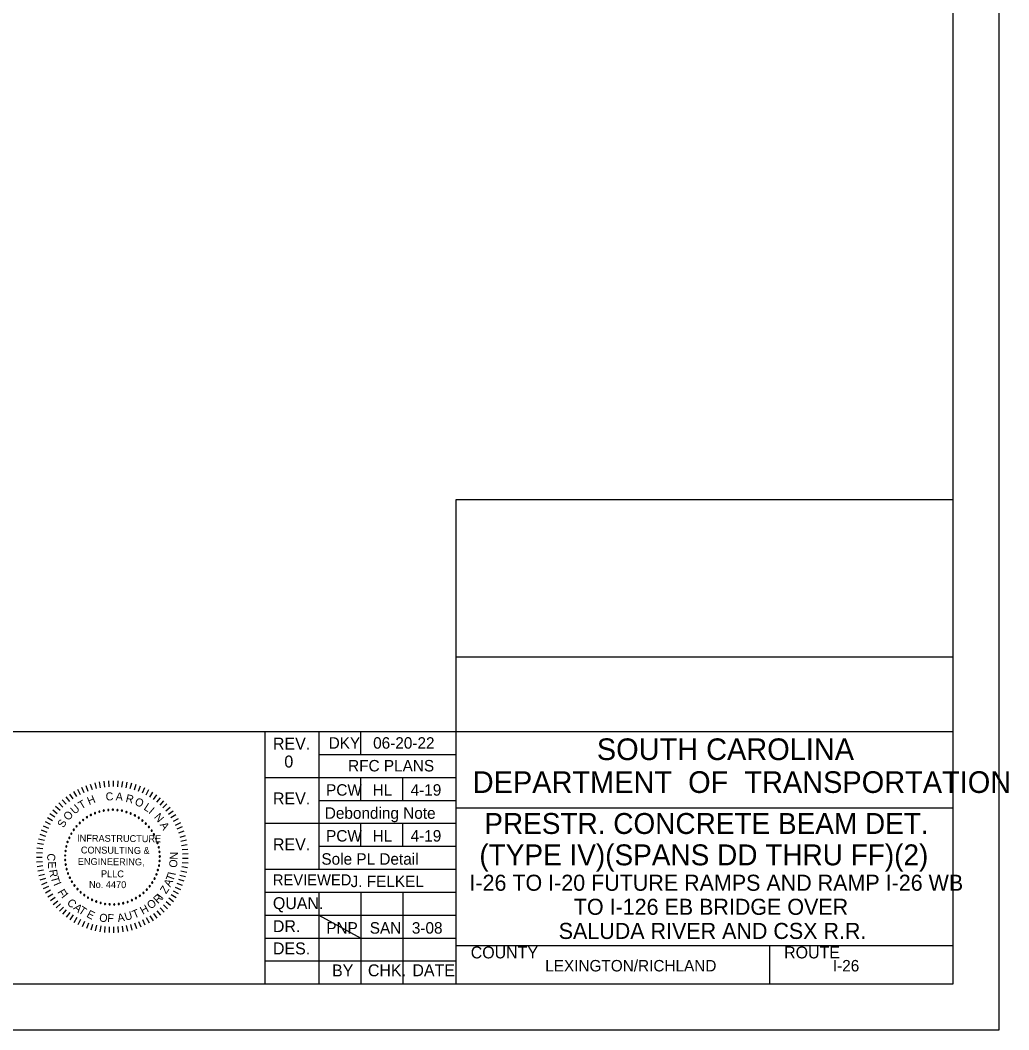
# Model space of a CAD drawing. Extents: x -50.5 to -14.4, y -52.6 to -30.6.
# Drawn here: x -25.19 to -14.41, y -52.58 to -41.58 of the extents above; entities that cross this region are included whole.
import ezdxf

# ---------------------------------------------------------------- set-up
doc = ezdxf.new("R2010")
doc.units = 0
for name, color, linetype in [('BR_BORDER LINES', 7, 'Continuous'), ('BR_TEXT', 7, 'Continuous'), ('Level 31', 7, 'Continuous')]:
    doc.layers.add(name, color=color, linetype=linetype)

msp = doc.modelspace()

# ---------------------------------------------------------------- linework, layer by layer
at = {"layer": 'BR_BORDER LINES'}
for p, q in [((-15.019, -52.081), (-15.019, -31.081)), ((-20.436, -52.081), (-20.436, -46.804)), ((-20.436, -46.804), (-15.019, -46.804)), ((-20.436, -48.519), (-15.019, -48.519)), ((-27.885, -49.331), (-22.52, -49.331)), ((-22.52, -52.081), (-22.52, -49.331)), ((-22.52, -49.331), (-15.019, -49.331)), ((-21.936, -49.331), (-21.936, -50.831)), ((-21.478, -49.581), (-21.478, -49.331)), ((-21.936, -49.581), (-20.436, -49.581)), ((-22.52, -49.831), (-20.436, -49.831)), ((-21.478, -50.081), (-21.478, -49.831)), ((-21.019, -50.081), (-21.019, -49.831)), ((-21.936, -50.081), (-20.436, -50.081)), ((-20.436, -50.164), (-20.436, -50.164)), ((-20.436, -50.164), (-15.019, -50.164)), ((-22.52, -50.331), (-20.436, -50.331)), ((-21.478, -50.581), (-21.478, -50.331)), ((-21.019, -50.581), (-21.019, -50.331)), ((-21.936, -50.581), (-20.436, -50.581)), ((-22.52, -50.831), (-20.436, -50.831)), ((-22.52, -51.081), (-20.436, -51.081)), ((-21.936, -51.081), (-21.936, -52.081)), ((-21.478, -51.081), (-21.478, -52.081)), ((-21.019, -51.081), (-21.019, -52.081)), ((-22.52, -51.331), (-20.436, -51.331)), ((-22.52, -51.581), (-20.436, -51.581)), ((-20.436, -51.664), (-15.019, -51.664)), ((-20.339, -51.664), (-15.019, -51.664)), ((-17.019, -52.081), (-17.019, -51.664)), ((-22.52, -51.831), (-20.436, -51.831)), ((-48.685, -52.081), (-15.019, -52.081))]:
    msp.add_line(p, q, dxfattribs=at)
at = {"layer": 'BR_TEXT'}
for p, q in [((-24.522, -49.939), (-24.496, -49.997)), ((-24.475, -49.92), (-24.453, -49.979)), ((-24.427, -49.903), (-24.408, -49.964)), ((-24.378, -49.89), (-24.363, -49.952)), ((-24.329, -49.88), (-24.318, -49.943)), ((-24.279, -49.873), (-24.272, -49.936)), ((-24.229, -49.869), (-24.225, -49.932)), ((-24.178, -49.867), (-24.179, -49.931)), ((-24.128, -49.87), (-24.132, -49.933)), ((-24.077, -49.875), (-24.086, -49.938)), ((-24.028, -49.883), (-24.04, -49.945)), ((-23.978, -49.894), (-23.994, -49.956)), ((-23.93, -49.908), (-23.95, -49.969)), ((-23.882, -49.925), (-23.906, -49.984)), ((-24.694, -50.042), (-24.655, -50.092)), ((-24.654, -50.012), (-24.618, -50.065)), ((-24.611, -49.985), (-24.578, -50.04)), ((-24.567, -49.96), (-24.538, -50.017)), ((-23.836, -49.945), (-23.863, -50.003)), ((-23.791, -49.968), (-23.821, -50.024)), ((-23.747, -49.993), (-23.781, -50.047)), ((-23.705, -50.021), (-23.742, -50.073)), ((-24.805, -50.146), (-24.757, -50.188)), ((-24.77, -50.109), (-24.725, -50.154)), ((-24.733, -50.074), (-24.691, -50.122)), ((-23.665, -50.052), (-23.705, -50.101)), ((-23.627, -50.085), (-23.67, -50.132)), ((-23.591, -50.12), (-23.636, -50.164)), ((-23.557, -50.157), (-23.605, -50.199)), ((-24.894, -50.267), (-24.84, -50.3)), ((-24.867, -50.225), (-24.815, -50.261)), ((-24.837, -50.184), (-24.787, -50.223)), ((-23.525, -50.197), (-23.576, -50.235)), ((-23.496, -50.238), (-23.549, -50.273)), ((-24.941, -50.357), (-24.883, -50.383)), ((-24.919, -50.311), (-24.863, -50.341)), ((-23.469, -50.281), (-23.524, -50.313)), ((-23.445, -50.325), (-23.502, -50.354)), ((-23.424, -50.371), (-23.483, -50.396)), ((-24.977, -50.451), (-24.916, -50.47)), ((-24.961, -50.403), (-24.901, -50.426)), ((-23.406, -50.418), (-23.466, -50.44)), ((-23.391, -50.466), (-23.452, -50.484)), ((-25.008, -50.599), (-24.945, -50.606)), ((-25.001, -50.549), (-24.938, -50.56)), ((-24.99, -50.5), (-24.928, -50.515)), ((-23.378, -50.515), (-23.44, -50.529)), ((-23.369, -50.565), (-23.431, -50.575)), ((-25.014, -50.7), (-24.95, -50.699)), ((-25.012, -50.649), (-24.949, -50.653)), ((-23.362, -50.615), (-23.426, -50.621)), ((-23.359, -50.665), (-23.422, -50.668)), ((-25.012, -50.75), (-24.948, -50.746)), ((-25.007, -50.801), (-24.944, -50.792)), ((-23.367, -50.816), (-23.43, -50.807)), ((-23.361, -50.766), (-23.425, -50.761)), ((-23.358, -50.716), (-23.422, -50.714)), ((-24.999, -50.85), (-24.936, -50.838)), ((-24.988, -50.9), (-24.926, -50.884)), ((-24.974, -50.948), (-24.913, -50.929)), ((-23.388, -50.915), (-23.449, -50.898)), ((-23.376, -50.866), (-23.438, -50.853)), ((-24.957, -50.996), (-24.898, -50.973)), ((-24.937, -51.042), (-24.88, -51.016)), ((-23.441, -51.056), (-23.499, -51.029)), ((-23.421, -51.01), (-23.48, -50.986)), ((-23.403, -50.963), (-23.463, -50.943)), ((-24.915, -51.087), (-24.859, -51.057)), ((-24.89, -51.131), (-24.835, -51.098)), ((-24.862, -51.173), (-24.81, -51.136)), ((-23.519, -51.186), (-23.571, -51.148)), ((-23.491, -51.144), (-23.544, -51.11)), ((-23.465, -51.101), (-23.52, -51.07)), ((-24.831, -51.214), (-24.782, -51.174)), ((-24.798, -51.252), (-24.751, -51.209)), ((-24.763, -51.288), (-24.719, -51.243)), ((-23.62, -51.299), (-23.664, -51.253)), ((-23.584, -51.263), (-23.63, -51.22)), ((-23.551, -51.226), (-23.6, -51.185)), ((-24.726, -51.322), (-24.685, -51.274)), ((-24.687, -51.354), (-24.648, -51.303)), ((-24.646, -51.383), (-24.61, -51.33)), ((-24.603, -51.41), (-24.571, -51.355)), ((-23.783, -51.418), (-23.814, -51.362)), ((-23.739, -51.392), (-23.774, -51.338)), ((-23.698, -51.363), (-23.735, -51.312)), ((-23.658, -51.332), (-23.698, -51.283)), ((-24.559, -51.434), (-24.53, -51.377)), ((-24.513, -51.456), (-24.488, -51.397)), ((-24.466, -51.474), (-24.444, -51.414)), ((-24.418, -51.49), (-24.4, -51.429)), ((-24.369, -51.502), (-24.355, -51.44)), ((-24.319, -51.512), (-24.309, -51.449)), ((-24.269, -51.519), (-24.263, -51.455)), ((-24.219, -51.522), (-24.217, -51.459)), ((-24.169, -51.523), (-24.17, -51.459)), ((-24.118, -51.52), (-24.123, -51.457)), ((-24.068, -51.514), (-24.077, -51.451)), ((-24.018, -51.506), (-24.031, -51.443)), ((-23.969, -51.494), (-23.986, -51.433)), ((-23.921, -51.479), (-23.941, -51.419)), ((-23.874, -51.462), (-23.898, -51.403)), ((-23.827, -51.441), (-23.855, -51.384))]:
    msp.add_line(p, q, dxfattribs=at)
for centre, start, end in [((-24.464, -50.265), 32.7576, 212.7576), ((-24.464, -50.265), 212.7576, 32.7576), ((-24.421, -50.24), 27.2191, 207.2191), ((-24.421, -50.24), 207.2191, 27.2191), ((-24.375, -50.22), 21.6807, 201.6807), ((-24.375, -50.22), 201.6807, 21.6807), ((-24.328, -50.204), 16.1422, 196.1422), ((-24.328, -50.204), 196.1422, 16.1422), ((-24.28, -50.192), 10.6038, 190.6038), ((-24.28, -50.192), 190.6038, 10.6038), ((-24.23, -50.186), 5.0653, 185.0653), ((-24.23, -50.186), 185.0653, 5.0653), ((-24.181, -50.184), 359.5268, 179.5268), ((-24.181, -50.184), 179.5268, 359.5268), ((-24.131, -50.187), 353.9884, 173.9884), ((-24.131, -50.187), 173.9884, 353.9884), ((-24.082, -50.194), 168.4499, 348.4499), ((-24.082, -50.194), 348.4499, 168.4499), ((-24.033, -50.207), 342.9114, 162.9114), ((-24.033, -50.207), 162.9114, 342.9114), ((-23.986, -50.224), 337.373, 157.373), ((-23.986, -50.224), 157.373, 337.373), ((-23.941, -50.245), 151.8345, 331.8345), ((-23.941, -50.245), 331.8345, 151.8345), ((-23.899, -50.271), 146.2961, 326.2961), ((-23.899, -50.271), 326.2961, 146.2961), ((-24.577, -50.363), 49.373, 229.373), ((-24.577, -50.363), 229.373, 49.373), ((-24.542, -50.327), 43.8345, 223.8345), ((-24.542, -50.327), 223.8345, 43.8345), ((-24.505, -50.294), 38.2961, 218.2961), ((-24.505, -50.294), 218.2961, 38.2961), ((-23.859, -50.301), 140.7576, 320.7576), ((-23.859, -50.301), 320.7576, 140.7576), ((-23.822, -50.334), 135.2191, 315.2191), ((-23.822, -50.334), 315.2191, 135.2191), ((-23.788, -50.371), 129.6807, 309.6807), ((-23.788, -50.371), 309.6807, 129.6807), ((-24.656, -50.489), 65.9884, 245.9884), ((-24.656, -50.489), 245.9884, 65.9884), ((-24.634, -50.444), 60.4499, 240.4499), ((-24.634, -50.444), 240.4499, 60.4499), ((-24.607, -50.402), 54.9114, 234.9114), ((-24.607, -50.402), 234.9114, 54.9114), ((-23.758, -50.411), 124.1422, 304.1422), ((-23.758, -50.411), 304.1422, 124.1422), ((-23.733, -50.453), 118.6038, 298.6038), ((-23.733, -50.453), 298.6038, 118.6038), ((-24.688, -50.583), 77.0653, 257.0653), ((-24.688, -50.583), 257.0653, 77.0653), ((-24.675, -50.535), 71.5268, 251.5268), ((-24.675, -50.535), 251.5268, 71.5268), ((-23.711, -50.498), 113.0653, 293.0653), ((-23.711, -50.498), 293.0653, 113.0653), ((-23.694, -50.545), 107.5268, 287.5268), ((-23.694, -50.545), 287.5268, 107.5268), ((-23.681, -50.593), 101.9884, 281.9884), ((-23.681, -50.593), 281.9884, 101.9884), ((-24.701, -50.682), 88.1422, 268.1422), ((-24.697, -50.632), 82.6038, 262.6038), ((-24.701, -50.682), 268.1422, 88.1422), ((-24.697, -50.632), 262.6038, 82.6038), ((-23.673, -50.642), 96.4499, 276.4499), ((-23.67, -50.692), 90.9114, 270.9114), ((-23.673, -50.642), 276.4499, 96.4499), ((-23.67, -50.692), 270.9114, 90.9114), ((-24.701, -50.731), 93.6807, 273.6807), ((-24.695, -50.781), 99.2191, 279.2191), ((-24.701, -50.731), 273.6807, 93.6807), ((-24.695, -50.781), 279.2191, 99.2191), ((-23.678, -50.791), 79.8345, 259.8345), ((-23.678, -50.791), 259.8345, 79.8345), ((-23.672, -50.742), 85.373, 265.373), ((-23.672, -50.742), 265.373, 85.373), ((-24.685, -50.83), 104.7576, 284.7576), ((-24.685, -50.83), 284.7576, 104.7576), ((-24.67, -50.877), 110.2961, 290.2961), ((-24.67, -50.877), 290.2961, 110.2961), ((-24.65, -50.923), 115.8345, 295.8345), ((-24.65, -50.923), 295.8345, 115.8345), ((-23.726, -50.933), 63.2191, 243.2191), ((-23.726, -50.933), 243.2191, 63.2191), ((-23.706, -50.887), 68.7576, 248.7576), ((-23.706, -50.887), 248.7576, 68.7576), ((-23.69, -50.84), 74.2961, 254.2961), ((-23.69, -50.84), 254.2961, 74.2961), ((-24.627, -50.967), 121.373, 301.373), ((-24.627, -50.967), 301.373, 121.373), ((-24.599, -51.008), 126.9114, 306.9114), ((-24.599, -51.008), 306.9114, 126.9114), ((-24.567, -51.047), 312.4499, 132.4499), ((-23.779, -51.017), 52.1422, 232.1422), ((-23.779, -51.017), 232.1422, 52.1422), ((-23.751, -50.976), 57.6807, 237.6807), ((-23.751, -50.976), 237.6807, 57.6807), ((-24.567, -51.047), 132.4499, 312.4499), ((-24.532, -51.082), 137.9884, 317.9884), ((-24.532, -51.082), 317.9884, 137.9884), ((-24.493, -51.113), 143.5268, 323.5268), ((-24.493, -51.113), 323.5268, 143.5268), ((-24.452, -51.141), 149.0653, 329.0653), ((-24.452, -51.141), 329.0653, 149.0653), ((-23.929, -51.146), 29.9884, 209.9884), ((-23.929, -51.146), 209.9884, 29.9884), ((-23.887, -51.12), 35.5268, 215.5268), ((-23.887, -51.12), 215.5268, 35.5268), ((-23.848, -51.089), 41.0653, 221.0653), ((-23.848, -51.089), 221.0653, 41.0653), ((-23.812, -51.054), 46.6038, 226.6038), ((-23.812, -51.054), 226.6038, 46.6038), ((-24.408, -51.165), 154.6038, 334.6038), ((-24.408, -51.165), 334.6038, 154.6038), ((-24.362, -51.184), 340.1422, 160.1422), ((-24.362, -51.184), 160.1422, 340.1422), ((-24.314, -51.199), 345.6807, 165.6807), ((-24.314, -51.199), 165.6807, 345.6807), ((-24.266, -51.209), 171.2191, 351.2191), ((-24.266, -51.209), 351.2191, 171.2191), ((-24.216, -51.214), 356.7576, 176.7576), ((-24.216, -51.214), 176.7576, 356.7576), ((-24.166, -51.215), 2.2961, 182.2961), ((-24.166, -51.215), 182.2961, 2.2961), ((-24.117, -51.21), 7.8345, 187.8345), ((-24.117, -51.21), 187.8345, 7.8345), ((-24.068, -51.201), 13.373, 193.373), ((-24.068, -51.201), 193.373, 13.373), ((-24.02, -51.188), 18.9114, 198.9114), ((-24.02, -51.188), 198.9114, 18.9114), ((-23.973, -51.169), 24.4499, 204.4499), ((-23.973, -51.169), 204.4499, 24.4499)]:
    msp.add_arc(centre, 0.00701, start, end, dxfattribs=at)
at = {"layer": 'Level 31'}
for p, q in [((-17.727, -50.604), (-17.727, -50.604)), ((-21.936, -51.331), (-21.478, -51.581))]:
    msp.add_line(p, q, dxfattribs=at)
msp.add_lwpolyline([(-50.519, -52.581), (-14.519, -52.581), (-14.519, -30.581), (-50.519, -30.581)], close=True, dxfattribs=at)

# ---------------------------------------------------------------- texts
at = {"layer": 'BR_TEXT'}
for s, height, p in [('REV.', 0.13, (-22.435, -49.528)), ('DKY', 0.125, (-21.828, -49.518)), ('06-20-22', 0.125, (-21.343, -49.518)), ('SOUTH CAROLINA', 0.23587, (-18.904, -49.642)), ('0', 0.13, (-22.311, -49.723)), ('RFC PLANS', 0.125, (-21.616, -49.766)), ('DEPARTMENT  OF  TRANSPORTATION', 0.23587, (-20.257, -50)), ('PCW', 0.125, (-21.856, -50.03)), ('HL', 0.125, (-21.349, -50.03)), (' 4-19', 0.125, (-20.981, -50.03)), ('REV.', 0.13, (-22.435, -50.125)), ('Debonding Note', 0.125, (-21.87, -50.282)), ('PRESTR. CONCRETE BEAM DET.', 0.228, (-20.131, -50.447)), ('PCW', 0.125, (-21.856, -50.53)), ('HL', 0.125, (-21.349, -50.53)), (' 4-19', 0.125, (-20.981, -50.53)), ('REV.', 0.13, (-22.435, -50.625)), ('(TYPE IV)(SPANS DD THRU FF)(2)', 0.228, (-20.185, -50.789)), ('Sole PL Detail', 0.125, (-21.907, -50.782)), ('REVIEWED', 0.12, (-22.436, -51.007)), ('J. FELKEL', 0.125, (-21.589, -51.026)), ('I-26 TO I-20 FUTURE RAMPS AND RAMP I-26 WB', 0.175, (-20.293, -51.066)), ('QUAN.', 0.13, (-22.436, -51.266)), ('TO I-126 EB BRIDGE OVER', 0.175, (-19.155, -51.328)), ('DR.', 0.13, (-22.436, -51.517)), ('PNP', 0.125, (-21.854, -51.533)), ('SAN', 0.125, (-21.38, -51.533)), ('3-08', 0.125, (-20.921, -51.533)), ('SALUDA RIVER AND CSX R.R.', 0.175, (-19.32, -51.591)), ('DES.', 0.13, (-22.435, -51.759)), ('COUNTY', 0.13, (-20.279, -51.803)), ('ROUTE', 0.13, (-16.862, -51.803)), ('BY', 0.13, (-21.791, -51.999)), ('CHK.', 0.13, (-21.4, -51.998)), ('DATE', 0.13, (-20.915, -51.997)), ('LEXINGTON/RICHLAND', 0.12499, (-19.467, -51.945)), ('I-26', 0.125, (-16.331, -51.945))]:
    msp.add_text(s, height=height, dxfattribs=at).set_placement(p)
for s, height, rotation, p in [('H', 0.0872, 22.7882, (-24.439, -50.134)), ('C', 0.0872, 4.7281, (-24.256, -50.085)), ('A', 0.0872, 355.6981, (-24.152, -50.08)), ('R', 0.0872, 346.6681, (-24.047, -50.097)), ('U', 0.0872, 40.8482, (-24.597, -50.238)), ('T', 0.0872, 31.8182, (-24.524, -50.182)), ('O', 0.0872, 337.638, (-23.95, -50.127)), ('L', 0.0872, 327.108, (-23.851, -50.177)), ('I', 0.0872, 319.578, (-23.798, -50.215)), ('O', 0.0872, 49.8782, (-24.664, -50.309)), ('N', 0.0872, 310.548, (-23.737, -50.266)), ('S', 0.0872, 58.9083, (-24.719, -50.387)), ('A', 0.0872, 301.5179, (-23.672, -50.348)), ('INFRASTRUCTURE', 0.07477, 359.5268, (-24.571, -50.53)), ('CONSULTING &', 0.07477, 359.5268, (-24.53, -50.659)), ('C', 0.0872, 267.025, (-24.894, -50.657)), ('ENGINEERING,', 0.07477, 359.5268, (-24.563, -50.784)), ('N', 0.0872, 89.2085, (-23.473, -50.727)), ('E', 0.0872, 273.025, (-24.89, -50.749)), ('O', 0.0872, 83.2085, (-23.484, -50.819)), ('R', 0.0872, 279.025, (-24.877, -50.841)), ('T', 0.0872, 285.025, (-24.86, -50.92)), ('PLLC', 0.0748, 359.5268, (-24.311, -50.918)), ('T', 0.0872, 69.3954, (-23.525, -50.97)), ('I', 0.0872, 77.9093, (-23.5, -50.903)), ('I', 0.0872, 293.7713, (-24.83, -50.993)), ('No. 4470', 0.0748, 359.5268, (-24.441, -51.034)), ('Z', 0.0872, 57.3954, (-23.6, -51.107)), ('A', 0.0872, 63.3954, (-23.556, -51.031)), ('F', 0.0872, 299.7713, (-24.789, -51.079)), ('I', 0.0872, 308.5268, (-24.747, -51.133)), ('R', 0.0872, 44.5268, (-23.69, -51.212)), ('I', 0.0872, 52.3339, (-23.641, -51.165)), ('C', 0.0872, 314.5268, (-24.688, -51.203)), ('A', 0.0872, 320.5268, (-24.618, -51.262)), ('T', 0.0872, 326.5268, (-24.564, -51.3)), ('H', 0.0872, 28.5268, (-23.855, -51.328)), ('O', 0.0872, 38.5268, (-23.767, -51.272)), ('E', 0.0872, 332.5268, (-24.475, -51.348)), ('O', 0.0872, 350.5268, (-24.335, -51.397)), ('F', 0.0872, 356.5268, (-24.244, -51.406)), ('A', 0.0872, 10.5268, (-24.124, -51.408)), ('U', 0.0872, 16.5268, (-24.04, -51.394)), ('T', 0.0872, 22.5268, (-23.948, -51.37))]:
    msp.add_text(s, height=height, rotation=rotation, dxfattribs=at).set_placement(p)

doc.saveas('drawing.dxf')
